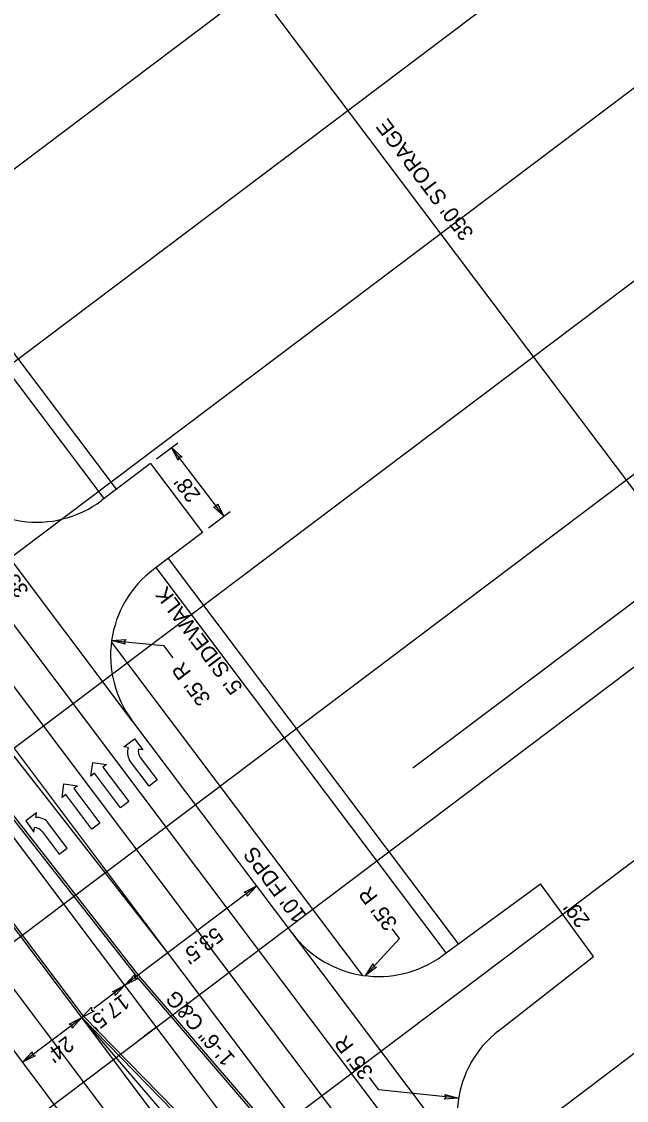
# Model space of a CAD drawing. Extents: x 1262309 to 1264352, y 775189 to 777755.
# Drawn here: x 1263600.9 to 1263797, y 776188.9 to 776538.6 of the extents above; entities that cross this region are included whole.
import ezdxf

# ---------------------------------------------------------------- set-up
doc = ezdxf.new("R2010")
doc.units = 0
for name, color, linetype in [('Default', 7, 'Continuous'), ('Prop Conc 1ft 6in Curb and Gutter', 7, 'Continuous'), ('Prop Conc 4in Sidewalk', 7, 'Continuous'), ('Prop Dimension', 7, 'Continuous'), ('Prop Dimension Text', 7, 'Continuous'), ('Prop EOT', 7, 'Continuous'), ('Prop Horizontal Alignment', 7, 'Continuous'), ('Prop Horizontal Alignment Tick Small', 7, 'Continuous'), ('Prop Lane Arrow CELL', 7, 'Continuous'), ('Prop Lane Lines', 7, 'Continuous'), ('Prop Paved Shoulder', 7, 'Continuous'), ('Prop Terminator CELL', 7, 'Continuous'), ('Scratch_Level_3', 7, 'Continuous')]:
    doc.layers.add(name, color=color, linetype=linetype)

msp = doc.modelspace()

# ---------------------------------------------------------------- linework, layer by layer
at = {"layer": 'Default'}
msp.add_line((1263644.58, 776212.73), (1263644.58, 776212.73), dxfattribs=at)
msp.add_line((1263644.58, 776212.73), (1263644.58, 776212.73), dxfattribs=at)
at = {"layer": 'Prop Conc 1ft 6in Curb and Gutter'}
for p, q in [((1263620.98, 776216.22), (1263413.7, 776491.42)), ((1263638.31, 776228.96), (1263462.6, 776453.08)), ((1263759.04, 776088.61), (1263638.31, 776228.96)), ((1263751.03, 776083.43), (1263620.92, 776216.3))]:
    msp.add_line(p, q, dxfattribs=at)
at = {"layer": 'Prop Conc 4in Sidewalk'}
for p, q in [((1263631.62, 776387.01), (1263511.75, 776546.15)), ((1263627.63, 776384), (1263508.98, 776541.52)), ((1263742.57, 776239.7), (1263648.46, 776364.64)), ((1263738.54, 776236.74), (1263644.47, 776361.63))]:
    msp.add_line(p, q, dxfattribs=at)
at = {"layer": 'Prop Dimension'}
for p, q in [((1263606.13, 776643.21), (1263816.71, 776363.63)), ((1263644.66, 776396.85), (1263651.51, 776402.06)), ((1263666.47, 776378.26), (1263649.52, 776400.54)), ((1263661.5, 776374.48), (1263668.46, 776379.77)), ((1263837.89, 776379.6), (1263727.72, 776296.6)), ((1263630.07, 776337.96), (1263646.87, 776336.42)), ((1263646.87, 776336.42), (1263649.88, 776332.43)), ((1263677.1, 776258.48), (1263624.28, 776218.69)), ((1263712.36, 776229.38), (1263723.37, 776241.47)), ((1263723.37, 776241.47), (1263721.03, 776244.57)), ((1263601.21, 776201.33), (1263620.38, 776215.77)), ((1263713.58, 776196.4), (1263716.59, 776192.41)), ((1263742.54, 776189.67), (1263716.59, 776192.41))]:
    msp.add_line(p, q, dxfattribs=at)
at = {"layer": 'Prop Dimension Text'}
for points in [[(1263630.32, 776224.18), (1263634.37, 776226.29), (1263631.25, 776222.91), (1263631.22, 776223.9)], [(1263616.33, 776213.66), (1263620.38, 776215.77), (1263617.26, 776212.39), (1263617.24, 776213.38)], [(1263605.26, 776203.44), (1263601.21, 776201.33), (1263604.33, 776204.71), (1263604.35, 776203.72)]]:
    msp.add_lwpolyline(points, close=True, dxfattribs=at)
at = {"layer": 'Prop EOT'}
for p, q in [((1263620.38, 776215.77), (1263391.43, 776519.73)), ((1263638.9, 776229.42), (1263464.15, 776452.33)), ((1263710.7, 776055.96), (1263423.46, 776437.32)), ((1263642.67, 776395.33), (1263626.83, 776383.4)), ((1263642.67, 776395.33), (1263659.51, 776372.97)), ((1263659.51, 776372.97), (1263643.67, 776361.03)), ((1263688.78, 776242.97), (1263636.67, 776312.15)), ((1263737.36, 776235.88), (1263769.07, 776259.12)), ((1263786.35, 776235.54), (1263769.07, 776259.12)), ((1263755.55, 776211.53), (1263786.35, 776235.54)), ((1263759.64, 776089.06), (1263638.9, 776229.42)), ((1263750.5, 776082.9), (1263620.38, 776215.77))]:
    msp.add_line(p, q, dxfattribs=at)
for centre, start, end in [((1263605.77, 776411.36), 216.9874, 306.9874), ((1263664.73, 776333.08), 126.9874, 216.9874), ((1263716.67, 776264.11), 216.9874, 306.2341), ((1263777.07, 776183.93), 127.9457, 216.9874)]:
    msp.add_arc(centre, 35, start, end, dxfattribs=at)
at = {"layer": 'Prop Horizontal Alignment'}
msp.add_line((1263830.93, 775965.32), (1263334.24, 776624.75), dxfattribs=at)
at = {"layer": 'Prop Horizontal Alignment Tick Small'}
msp.add_line((1263644.58, 776212.73), (1263640.59, 776209.72), dxfattribs=at)
at = {"layer": 'Prop Lane Arrow CELL'}
for p, q in [((1263633.99, 776303.5), (1263637.48, 776306.18)), ((1263637.48, 776306.18), (1263640.22, 776302.62)), ((1263635.46, 776303.29), (1263633.99, 776303.5)), ((1263640.22, 776302.62), (1263638.75, 776302.83)), ((1263623.37, 776294.08), (1263623.96, 776298.46)), ((1263623.96, 776298.46), (1263628.41, 776297.87)), ((1263628.41, 776297.87), (1263627.21, 776296.97)), ((1263642.21, 776290.84), (1263635.86, 776299.27)), ((1263639.34, 776300.14), (1263644.85, 776292.83)), ((1263624.57, 776294.99), (1263623.37, 776294.08)), ((1263633, 776283.8), (1263624.57, 776294.99)), ((1263627.21, 776296.97), (1263635.63, 776285.79)), ((1263614.03, 776287.14), (1263614.61, 776291.52)), ((1263614.61, 776291.52), (1263619.06, 776290.93)), ((1263619.06, 776290.93), (1263617.86, 776290.03)), ((1263644.85, 776292.83), (1263642.21, 776290.84)), ((1263615.23, 776288.05), (1263614.03, 776287.14)), ((1263623.65, 776276.86), (1263615.23, 776288.05)), ((1263617.86, 776290.03), (1263626.28, 776278.85)), ((1263635.63, 776285.79), (1263633, 776283.8)), ((1263605.76, 776282.14), (1263602.21, 776279.53)), ((1263605.55, 776280.67), (1263605.76, 776282.14)), ((1263602.21, 776279.53), (1263604.88, 776275.91)), ((1263604.88, 776275.91), (1263605.09, 776277.38)), ((1263607.51, 776276.07), (1263613.01, 776268.76)), ((1263615.65, 776270.75), (1263609.3, 776279.18)), ((1263626.28, 776278.85), (1263623.65, 776276.86)), ((1263613.01, 776268.76), (1263615.65, 776270.75))]:
    msp.add_line(p, q, dxfattribs=at)
for centre, radius, start, end in [((1263640.47, 776301.75), 5.25, 162.9996, 208.3113), ((1263641.94, 776302.11), 3.27, 167.3292, 216.9874), ((1263605.65, 776275.43), 5.25, 45.6635, 90.9752), ((1263604.9, 776274.12), 3.27, 36.9874, 86.6456)]:
    msp.add_arc(centre, radius, start, end, dxfattribs=at)
at = {"layer": 'Prop Lane Lines'}
for p, q in [((1263648.34, 776236.82), (1263473.59, 776459.73)), ((1263794, 775965.32), (1263433.04, 776444.54)), ((1263636.77, 776312.02), (1263577.82, 776390.28)), ((1263685.9, 776226.85), (1263568.24, 776383.06)), ((1263676.32, 776219.63), (1263558.65, 776375.84)), ((1263648.34, 776236.82), (1263549.06, 776368.64)), ((1263749.05, 776162.96), (1263688.78, 776242.97)), ((1263759.64, 776089.06), (1263648.34, 776236.82)), ((1263757.94, 776131.2), (1263685.9, 776226.85)), ((1263748.36, 776123.98), (1263676.32, 776219.63)), ((1263731.68, 776068), (1263620.38, 776215.77)), ((1263741.09, 776075.45), (1263620.38, 776215.77))]:
    msp.add_line(p, q, dxfattribs=at)
at = {"layer": 'Prop Paved Shoulder'}
msp.add_line((1263711.44, 776229.51), (1263630.02, 776337.6), dxfattribs=at)
at = {"layer": 'Prop Terminator CELL'}
for points in [[(1263651.63, 776396.49), (1263649.52, 776400.54), (1263652.9, 776397.43), (1263651.91, 776397.4)], [(1263664.36, 776382.31), (1263666.47, 776378.26), (1263663.1, 776381.38), (1263664.08, 776381.4)], [(1263634.48, 776336.77), (1263630.07, 776337.96), (1263634.65, 776338.34), (1263634, 776337.6)], [(1263673.04, 776256.39), (1263677.1, 776258.48), (1263673.97, 776255.12), (1263673.95, 776256.1)], [(1263715.96, 776232.18), (1263712.36, 776229.38), (1263714.82, 776233.26), (1263715.02, 776232.3)], [(1263638.43, 776228.38), (1263634.37, 776226.29), (1263637.5, 776229.65), (1263637.52, 776228.67)], [(1263624.44, 776217.86), (1263620.38, 776215.77), (1263623.51, 776219.13), (1263623.54, 776218.15)], [(1263738.15, 776190.91), (1263742.54, 776189.67), (1263737.96, 776189.35), (1263738.62, 776190.09)]]:
    msp.add_lwpolyline(points, close=True, dxfattribs=at)
at = {"layer": 'Scratch_Level_3'}
for p, q in [((1263296.23, 776263.33), (1263791.33, 776636.25)), ((1263326.32, 776223.39), (1263821.42, 776596.31)), ((1263356.4, 776183.46), (1263851.5, 776556.37)), ((1263386.48, 776143.52), (1263881.58, 776516.43)), ((1263416.56, 776103.58), (1263911.66, 776476.49)), ((1263446.64, 776063.64), (1263941.74, 776436.56)), ((1263476.73, 776023.7), (1263971.83, 776396.62)), ((1263506.81, 775983.76), (1264001.91, 776356.68))]:
    msp.add_line(p, q, dxfattribs=at)

# ---------------------------------------------------------------- texts
at = {"layer": 'Prop Dimension'}
for s, rotation, p in [("35' R", 127.0213, (1263603.5, 776354.29)), ("35' R", 127.0213, (1263662.43, 776319.19)), ("35' R", 127.0213, (1263722.99, 776246.4)), ('1\'-6" C&G', 131.2048, (1263670.37, 776202.77)), ("35' R", 127.0213, (1263715.16, 776198.14))]:
    msp.add_text(s, height=5, rotation=rotation, dxfattribs=at).set_placement(p)
at = {"layer": 'Prop Dimension Text'}
for s, rotation, p in [("350' STORAGE", 126.9874, (1263747.74, 776470.05)), ("28'", 127.0213, (1263659.16, 776385.2)), ("5' SIDEWALK", 127.0213, (1263672.84, 776322.86)), ("10' FDPS", 126.9874, (1263693.49, 776248.98)), ("29'", 127.0213, (1263785.42, 776247.31)), ("53.5'", 217.2584, (1263663.78, 776245.39)), ("17.5'", 217.2584, (1263633.5, 776223.69)), ("24'", 217.2584, (1263615.42, 776210.06))]:
    msp.add_text(s, height=5, rotation=rotation, dxfattribs=at).set_placement(p)

doc.saveas('drawing.dxf')
